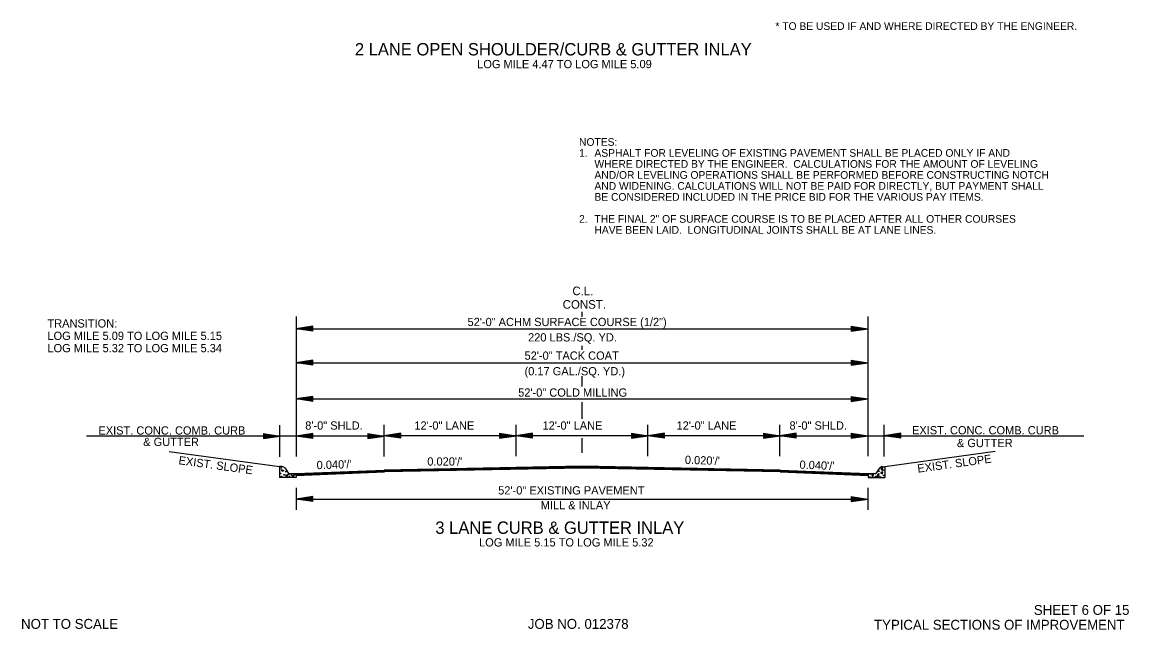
# Model space of a CAD drawing. Extents: x 542112 to 1930787, y -1968972 to 596640.
# Drawn here: x 546438 to 547445, y -1948192 to -1947639 of the extents above; entities that cross this region are included whole.
import ezdxf

# ---------------------------------------------------------------- set-up
doc = ezdxf.new("R2010")
doc.units = 0
for name, color, linetype in [('R_Border Notes', 7, 'Continuous'), ('R_Border Prem', 7, 'Continuous'), ('R_Draft', 7, 'Continuous')]:
    doc.layers.add(name, color=color, linetype=linetype)

msp = doc.modelspace()

# ---------------------------------------------------------------- linework, layer by layer
at = {"layer": 'R_Draft'}
for p, q in [((546947.1, -1947907), (546947.1, -1947902.6)), ((546687.1, -1947906.7), (546687.1, -1948034.1)), ((546702.1, -1947915.7), (546687.1, -1947918)), ((546687.1, -1947918), (547207.1, -1947918)), ((546702.1, -1947920.2), (546687.1, -1947918)), ((546702.1, -1947916.1), (546689.7, -1947918)), ((546702.1, -1947919.8), (546689.7, -1947918)), ((546702.1, -1947916.5), (546692.2, -1947918)), ((546702.1, -1947919.4), (546692.2, -1947918)), ((546702.1, -1947916.8), (546694.7, -1947918)), ((546702.1, -1947919.1), (546694.7, -1947918)), ((546702.1, -1947917.2), (546697.3, -1947918)), ((546702.1, -1947918.7), (546697.3, -1947918)), ((546702.1, -1947917.6), (546699.8, -1947918)), ((546702.1, -1947918.3), (546699.8, -1947918)), ((546702.1, -1947920.2), (546702.1, -1947915.7)), ((547192.1, -1947915.7), (547207.1, -1947918)), ((547192.1, -1947915.7), (547192.1, -1947920.2)), ((547192.1, -1947916.1), (547204.6, -1947918)), ((547192.1, -1947916.5), (547202, -1947918)), ((547192.1, -1947916.8), (547199.5, -1947918)), ((547192.1, -1947917.2), (547196.9, -1947918)), ((547192.1, -1947917.6), (547194.4, -1947918)), ((547192.1, -1947920.2), (547207.1, -1947918)), ((547192.1, -1947918.7), (547196.9, -1947918)), ((547192.1, -1947919.4), (547202, -1947918)), ((547192.1, -1947919.8), (547204.6, -1947918)), ((547192.1, -1947919.1), (547199.5, -1947918)), ((547192.1, -1947918.3), (547194.4, -1947918)), ((546947.1, -1947937.1), (546947.1, -1947933.4)), ((546702.1, -1947946.6), (546687.1, -1947948.8)), ((546687.1, -1947948.8), (547207.1, -1947948.8)), ((546702.1, -1947951.1), (546687.1, -1947948.8)), ((546702.1, -1947946.9), (546689.7, -1947948.8)), ((546702.1, -1947950.7), (546689.7, -1947948.8)), ((546702.1, -1947947.3), (546692.2, -1947948.8)), ((546702.1, -1947950.3), (546692.2, -1947948.8)), ((546702.1, -1947947.7), (546694.7, -1947948.8)), ((546702.1, -1947949.9), (546694.7, -1947948.8)), ((546702.1, -1947948.1), (546697.3, -1947948.8)), ((546702.1, -1947949.5), (546697.3, -1947948.8)), ((546702.1, -1947948.5), (546699.8, -1947948.8)), ((546702.1, -1947949.2), (546699.8, -1947948.8)), ((546702.1, -1947951.1), (546702.1, -1947946.6)), ((547192.1, -1947946.6), (547207.1, -1947948.8)), ((547192.1, -1947946.6), (547192.1, -1947951.1)), ((547192.1, -1947946.9), (547204.6, -1947948.8)), ((547192.1, -1947947.3), (547202, -1947948.8)), ((547192.1, -1947947.7), (547199.5, -1947948.8)), ((547192.1, -1947948.1), (547196.9, -1947948.8)), ((547192.1, -1947948.5), (547194.4, -1947948.8)), ((547192.1, -1947951.1), (547207.1, -1947948.8)), ((547192.1, -1947949.6), (547196.9, -1947948.8)), ((547192.1, -1947950.3), (547202, -1947948.8)), ((547192.1, -1947950.7), (547204.6, -1947948.8)), ((547192.1, -1947949.9), (547199.5, -1947948.8)), ((547192.1, -1947949.2), (547194.4, -1947948.8)), ((546947.1, -1947970.5), (546947.1, -1947961.2)), ((546702.1, -1947979.5), (546687.1, -1947981.8)), ((546687.1, -1947981.8), (547207.1, -1947981.8)), ((546702.1, -1947984), (546687.1, -1947981.8)), ((546702.1, -1947979.9), (546689.7, -1947981.8)), ((546702.1, -1947983.6), (546689.7, -1947981.8)), ((546702.1, -1947980.3), (546692.2, -1947981.8)), ((546702.1, -1947983.2), (546692.2, -1947981.8)), ((546702.1, -1947980.6), (546694.7, -1947981.8)), ((546702.1, -1947982.9), (546694.7, -1947981.8)), ((546702.1, -1947981), (546697.3, -1947981.8)), ((546702.1, -1947982.5), (546697.3, -1947981.8)), ((546702.1, -1947981.4), (546699.8, -1947981.8)), ((546702.1, -1947982.1), (546699.8, -1947981.8)), ((546702.1, -1947984), (546702.1, -1947979.5)), ((547192.1, -1947979.5), (547207.1, -1947981.8)), ((547192.1, -1947979.5), (547192.1, -1947984)), ((547192.1, -1947979.9), (547204.6, -1947981.8)), ((547192.1, -1947980.3), (547202, -1947981.8)), ((547192.1, -1947980.6), (547199.5, -1947981.8)), ((547192.1, -1947981), (547196.9, -1947981.8)), ((547192.1, -1947981.4), (547194.4, -1947981.8)), ((547192.1, -1947984), (547207.1, -1947981.8)), ((547192.1, -1947982.5), (547196.9, -1947981.8)), ((547192.1, -1947983.2), (547202, -1947981.8)), ((547192.1, -1947983.6), (547204.6, -1947981.8)), ((547192.1, -1947982.9), (547199.5, -1947981.8)), ((547192.1, -1947982.1), (547194.4, -1947981.8)), ((546947.1, -1947999.9), (546947.1, -1947984.7)), ((546657.1, -1948013.2), (546672.1, -1948015.5)), ((546657.1, -1948013.2), (546657.1, -1948017.7)), ((546657.1, -1948013.6), (546669.6, -1948015.5)), ((546657.1, -1948014), (546667.1, -1948015.5)), ((546672.1, -1948034.3), (546672.1, -1948005.6)), ((546702.1, -1948013.2), (546687.1, -1948015.5)), ((546702.1, -1948013.6), (546689.7, -1948015.5)), ((546702.1, -1948014), (546692.2, -1948015.5)), ((546702.1, -1948017.7), (546702.1, -1948013.2)), ((546752.1, -1948013.2), (546767.1, -1948015.5)), ((546752.1, -1948013.2), (546752.1, -1948017.7)), ((546752.1, -1948013.6), (546764.6, -1948015.5)), ((546752.1, -1948014), (546762.1, -1948015.5)), ((546767.1, -1948033.9), (546767.1, -1948005.4)), ((546767.1, -1948034.1), (546767.1, -1948005.4)), ((546782.1, -1948013), (546767.1, -1948015.3)), ((546782.1, -1948013.4), (546769.7, -1948015.3)), ((546782.1, -1948013.8), (546772.2, -1948015.3)), ((546782.1, -1948017.5), (546782.1, -1948013)), ((546872.1, -1948013), (546887.1, -1948015.3)), ((546872.1, -1948013), (546872.1, -1948017.5)), ((546872.1, -1948013.4), (546884.6, -1948015.3)), ((546872.1, -1948013.8), (546882.1, -1948015.3)), ((546887.1, -1948033.9), (546887.1, -1948005.4)), ((546902.1, -1948013), (546887.1, -1948015.3)), ((546902.1, -1948013.4), (546889.7, -1948015.3)), ((546902.1, -1948013.8), (546892.2, -1948015.3)), ((546902.1, -1948017.5), (546902.1, -1948013)), ((546992.1, -1948013), (547007.1, -1948015.3)), ((546992.1, -1948013), (546992.1, -1948017.5)), ((546992.1, -1948013.4), (547004.6, -1948015.3)), ((546992.1, -1948013.8), (547002.1, -1948015.3)), ((547007.1, -1948033.9), (547007.1, -1948005.4)), ((547022.1, -1948013), (547007.1, -1948015.3)), ((547022.1, -1948013.4), (547009.7, -1948015.3)), ((547022.1, -1948013.8), (547012.2, -1948015.3)), ((547022.1, -1948017.5), (547022.1, -1948013)), ((547112.1, -1948013), (547127.1, -1948015.3)), ((547112.1, -1948013), (547112.1, -1948017.5)), ((547112.1, -1948013.4), (547124.6, -1948015.3)), ((547112.1, -1948013.8), (547122.1, -1948015.3)), ((547127.1, -1948033.9), (547127.1, -1948005.4)), ((547142.1, -1948013), (547127.1, -1948015.3)), ((547142.1, -1948013.4), (547129.7, -1948015.3)), ((547142.1, -1948013.8), (547132.2, -1948015.3)), ((547142.1, -1948017.5), (547142.1, -1948013)), ((547192.1, -1948013), (547207.1, -1948015.3)), ((547192.1, -1948013), (547192.1, -1948017.5)), ((547192.1, -1948013.4), (547204.6, -1948015.3)), ((547192.1, -1948013.8), (547202.1, -1948015.3)), ((547222.1, -1948034.1), (547222.1, -1948005.4)), ((547237.1, -1948013), (547222.1, -1948015.3)), ((547237.1, -1948013.4), (547224.7, -1948015.3)), ((547237.1, -1948013.8), (547227.2, -1948015.3)), ((547237.1, -1948017.5), (547237.1, -1948013)), ((546687.1, -1948015.5), (546496.3, -1948015.5)), ((546657.1, -1948014.3), (546664.6, -1948015.5)), ((546657.1, -1948014.7), (546662, -1948015.5)), ((546657.1, -1948015.1), (546659.5, -1948015.5)), ((546657.1, -1948017.7), (546672.1, -1948015.5)), ((546657.1, -1948016.2), (546662, -1948015.5)), ((546657.1, -1948017), (546667.1, -1948015.5)), ((546657.1, -1948017.3), (546669.6, -1948015.5)), ((546657.1, -1948016.6), (546664.6, -1948015.5)), ((546657.1, -1948015.8), (546659.5, -1948015.5)), ((546767.1, -1948015.5), (546687.1, -1948015.5)), ((546702.1, -1948017.7), (546687.1, -1948015.5)), ((546702.1, -1948017.3), (546689.7, -1948015.5)), ((546702.1, -1948017), (546692.2, -1948015.5)), ((546702.1, -1948014.3), (546694.7, -1948015.5)), ((546702.1, -1948016.6), (546694.7, -1948015.5)), ((546702.1, -1948014.7), (546697.3, -1948015.5)), ((546702.1, -1948016.2), (546697.3, -1948015.5)), ((546702.1, -1948015.1), (546699.8, -1948015.5)), ((546702.1, -1948015.8), (546699.8, -1948015.5)), ((546752.1, -1948014.3), (546759.6, -1948015.5)), ((546752.1, -1948014.7), (546757, -1948015.5)), ((546752.1, -1948015.1), (546754.5, -1948015.5)), ((546752.1, -1948017.7), (546767.1, -1948015.5)), ((546752.1, -1948016.2), (546757, -1948015.5)), ((546752.1, -1948017), (546762.1, -1948015.5)), ((546752.1, -1948017.3), (546764.6, -1948015.5)), ((546752.1, -1948016.6), (546759.6, -1948015.5)), ((546752.1, -1948015.8), (546754.5, -1948015.5)), ((546887.1, -1948015.3), (546767.1, -1948015.3)), ((546782.1, -1948017.5), (546767.1, -1948015.3)), ((546782.1, -1948017.2), (546769.7, -1948015.3)), ((546782.1, -1948016.8), (546772.2, -1948015.3)), ((546782.1, -1948014.2), (546774.7, -1948015.3)), ((546782.1, -1948016.4), (546774.7, -1948015.3)), ((546782.1, -1948014.6), (546777.3, -1948015.3)), ((546782.1, -1948016), (546777.3, -1948015.3)), ((546782.1, -1948014.9), (546779.8, -1948015.3)), ((546782.1, -1948015.6), (546779.8, -1948015.3)), ((546872.1, -1948014.2), (546879.6, -1948015.3)), ((546872.1, -1948014.6), (546877, -1948015.3)), ((546872.1, -1948014.9), (546874.5, -1948015.3)), ((546872.1, -1948017.5), (546887.1, -1948015.3)), ((546872.1, -1948016), (546877, -1948015.3)), ((546872.1, -1948016.8), (546882.1, -1948015.3)), ((546872.1, -1948017.2), (546884.6, -1948015.3)), ((546872.1, -1948016.4), (546879.6, -1948015.3)), ((546872.1, -1948015.6), (546874.5, -1948015.3)), ((547007.1, -1948015.3), (546887.1, -1948015.3)), ((546902.1, -1948017.5), (546887.1, -1948015.3)), ((546902.1, -1948017.2), (546889.7, -1948015.3)), ((546902.1, -1948016.8), (546892.2, -1948015.3)), ((546902.1, -1948014.2), (546894.7, -1948015.3)), ((546902.1, -1948016.4), (546894.7, -1948015.3)), ((546902.1, -1948014.6), (546897.3, -1948015.3)), ((546902.1, -1948016), (546897.3, -1948015.3)), ((546902.1, -1948014.9), (546899.8, -1948015.3)), ((546902.1, -1948015.6), (546899.8, -1948015.3)), ((546947.1, -1948030.7), (546947.1, -1948017.4)), ((546992.1, -1948014.2), (546999.6, -1948015.3)), ((546992.1, -1948014.6), (546997, -1948015.3)), ((546992.1, -1948014.9), (546994.5, -1948015.3)), ((546992.1, -1948017.5), (547007.1, -1948015.3)), ((546992.1, -1948016), (546997, -1948015.3)), ((546992.1, -1948016.8), (547002.1, -1948015.3)), ((546992.1, -1948017.2), (547004.6, -1948015.3)), ((546992.1, -1948016.4), (546999.6, -1948015.3)), ((546992.1, -1948015.6), (546994.5, -1948015.3)), ((547127.1, -1948015.3), (547007.1, -1948015.3)), ((547022.1, -1948017.5), (547007.1, -1948015.3)), ((547022.1, -1948017.2), (547009.7, -1948015.3)), ((547022.1, -1948016.8), (547012.2, -1948015.3)), ((547022.1, -1948014.2), (547014.7, -1948015.3)), ((547022.1, -1948016.4), (547014.7, -1948015.3)), ((547022.1, -1948014.6), (547017.3, -1948015.3)), ((547022.1, -1948016), (547017.3, -1948015.3)), ((547022.1, -1948014.9), (547019.8, -1948015.3)), ((547022.1, -1948015.6), (547019.8, -1948015.3)), ((547112.1, -1948014.2), (547119.6, -1948015.3)), ((547112.1, -1948014.6), (547117, -1948015.3)), ((547112.1, -1948014.9), (547114.5, -1948015.3)), ((547112.1, -1948017.5), (547127.1, -1948015.3)), ((547112.1, -1948016), (547117, -1948015.3)), ((547112.1, -1948016.8), (547122.1, -1948015.3)), ((547112.1, -1948017.2), (547124.6, -1948015.3)), ((547112.1, -1948016.4), (547119.6, -1948015.3)), ((547112.1, -1948015.6), (547114.5, -1948015.3)), ((547127.1, -1948015.3), (547207.1, -1948015.3)), ((547142.1, -1948017.5), (547127.1, -1948015.3)), ((547142.1, -1948017.2), (547129.7, -1948015.3)), ((547142.1, -1948016.8), (547132.2, -1948015.3)), ((547142.1, -1948014.2), (547134.7, -1948015.3)), ((547142.1, -1948016.4), (547134.7, -1948015.3)), ((547142.1, -1948014.6), (547137.3, -1948015.3)), ((547142.1, -1948016), (547137.3, -1948015.3)), ((547142.1, -1948014.9), (547139.8, -1948015.3)), ((547142.1, -1948015.6), (547139.8, -1948015.3)), ((547192.1, -1948014.2), (547199.6, -1948015.3)), ((547192.1, -1948014.6), (547197, -1948015.3)), ((547192.1, -1948014.9), (547194.5, -1948015.3)), ((547192.1, -1948017.5), (547207.1, -1948015.3)), ((547192.1, -1948016), (547197, -1948015.3)), ((547192.1, -1948016.8), (547202.1, -1948015.3)), ((547192.1, -1948017.2), (547204.6, -1948015.3)), ((547192.1, -1948016.4), (547199.6, -1948015.3)), ((547192.1, -1948015.6), (547194.5, -1948015.3)), ((547207.1, -1948015.3), (547403.8, -1948015.3)), ((547237.1, -1948017.5), (547222.1, -1948015.3)), ((547237.1, -1948017.2), (547224.7, -1948015.3)), ((547237.1, -1948016.8), (547227.2, -1948015.3)), ((547237.1, -1948014.2), (547229.7, -1948015.3)), ((547237.1, -1948016.4), (547229.7, -1948015.3)), ((547237.1, -1948014.6), (547232.3, -1948015.3)), ((547237.1, -1948016), (547232.3, -1948015.3)), ((547237.1, -1948014.9), (547234.8, -1948015.3)), ((547237.1, -1948015.6), (547234.8, -1948015.3)), ((546571.4, -1948029.5), (546671.9, -1948043.3)), ((547323.1, -1948029.6), (547222.6, -1948043.4)), ((546674.1, -1948043.3), (546671.9, -1948043.3)), ((546671.9, -1948043.3), (546671.9, -1948053.2)), ((546947.1, -1948042.9), (546767.1, -1948046.5)), ((546947.2, -1948043.2), (546767.2, -1948046.8)), ((546947.2, -1948043.5), (546767.2, -1948047.1)), ((546947.2, -1948043.8), (546767.2, -1948047.4)), ((546947.2, -1948044.1), (546767.2, -1948047.7)), ((547127.3, -1948046.5), (546947.1, -1948042.9)), ((547127.3, -1948046.8), (546947.1, -1948043.2)), ((547127.3, -1948047.1), (546947.1, -1948043.5)), ((547127.3, -1948047.4), (546947.1, -1948043.8)), ((547127.3, -1948047.7), (546947.1, -1948044.1)), ((547220.5, -1948043.4), (547222.6, -1948043.4)), ((547222.6, -1948043.4), (547222.6, -1948053.2)), ((546686.9, -1948053.2), (546671.9, -1948053.2)), ((546676.9, -1948044.8), (546680, -1948049.7)), ((546680, -1948049.7), (546686.9, -1948049.7)), ((546686.9, -1948049.7), (546767.1, -1948046.5)), ((546686.9, -1948050), (546767.2, -1948046.8)), ((546686.9, -1948050.3), (546767.2, -1948047.1)), ((546686.9, -1948050.6), (546767.2, -1948047.4)), ((546686.9, -1948050.9), (546767.2, -1948047.7)), ((546686.9, -1948051.2), (546767.2, -1948048)), ((546686.9, -1948051.4), (546767.2, -1948048.2)), ((546686.9, -1948049.7), (546686.9, -1948051.4)), ((546686.9, -1948049.7), (546686.9, -1948053.2)), ((546947.2, -1948044.4), (546767.2, -1948048)), ((546947.2, -1948044.6), (546767.2, -1948048.2)), ((547127.3, -1948048), (546947.1, -1948044.4)), ((547127.3, -1948048.2), (546947.1, -1948044.6)), ((547127.3, -1948046.5), (547207.6, -1948049.7)), ((547127.3, -1948046.8), (547207.6, -1948050)), ((547127.3, -1948047.1), (547207.6, -1948050.3)), ((547127.3, -1948047.4), (547207.6, -1948050.6)), ((547127.3, -1948047.7), (547207.6, -1948050.9)), ((547127.3, -1948048), (547207.6, -1948051.2)), ((547127.3, -1948048.2), (547207.6, -1948051.4)), ((547207.6, -1948049.7), (547207.6, -1948051.4)), ((547207.6, -1948051.4), (547207.6, -1948049.7)), ((547207.6, -1948049.7), (547207.6, -1948051.4)), ((547207.6, -1948051.4), (547207.6, -1948049.7)), ((547207.6, -1948049.7), (547214.6, -1948049.7)), ((547207.6, -1948049.7), (547207.6, -1948053.2)), ((547207.6, -1948053.2), (547222.6, -1948053.2)), ((547217.6, -1948044.9), (547214.6, -1948049.7)), ((546687.1, -1948062.5), (546687.1, -1948082.5)), ((547207.1, -1948062.5), (547207.1, -1948082.5)), ((546702.1, -1948070.5), (546687.1, -1948072.8)), ((546687.1, -1948072.8), (547207.1, -1948072.8)), ((546702.1, -1948075), (546687.1, -1948072.8)), ((546702.1, -1948070.9), (546689.7, -1948072.8)), ((546702.1, -1948074.6), (546689.7, -1948072.8)), ((546702.1, -1948071.3), (546692.2, -1948072.8)), ((546702.1, -1948074.2), (546692.2, -1948072.8)), ((546702.1, -1948071.6), (546694.7, -1948072.8)), ((546702.1, -1948073.9), (546694.7, -1948072.8)), ((546702.1, -1948072), (546697.3, -1948072.8)), ((546702.1, -1948073.5), (546697.3, -1948072.8)), ((546702.1, -1948072.4), (546699.8, -1948072.8)), ((546702.1, -1948073.1), (546699.8, -1948072.8)), ((546702.1, -1948075), (546702.1, -1948070.5)), ((547192.1, -1948070.5), (547207.1, -1948072.8)), ((547192.1, -1948070.5), (547192.1, -1948075)), ((547192.1, -1948070.9), (547204.6, -1948072.8)), ((547192.1, -1948071.3), (547202.1, -1948072.8)), ((547192.1, -1948071.6), (547199.6, -1948072.8)), ((547192.1, -1948072), (547197, -1948072.8)), ((547192.1, -1948072.4), (547194.5, -1948072.8)), ((547192.1, -1948075), (547207.1, -1948072.8)), ((547192.1, -1948073.5), (547197, -1948072.8)), ((547192.1, -1948074.2), (547202.1, -1948072.8)), ((547192.1, -1948074.6), (547204.6, -1948072.8)), ((547192.1, -1948073.9), (547199.6, -1948072.8)), ((547192.1, -1948073.1), (547194.5, -1948072.8))]:
    msp.add_line(p, q, dxfattribs=at)
for points in [[(547207.1, -1947906.7), (547207.1, -1948033.9)], [(546675.8, -1948046.8), (546674.1, -1948047.9), (546673.7, -1948046.1), (546675.6, -1948046.8)], [(546678.6, -1948052.7), (546677.5, -1948051), (546679.3, -1948050.6), (546678.6, -1948052.5)], [(546684.3, -1948053.1), (546683.2, -1948051.3), (546684.9, -1948050.9), (546684.3, -1948052.8)], [(547211.3, -1948053.2), (547212.5, -1948051.4), (547210.7, -1948051), (547211.3, -1948052.9)], [(547216.4, -1948052.9), (547217.6, -1948051.1), (547215.8, -1948050.8), (547216.4, -1948052.7)], [(547218.7, -1948048.8), (547220.4, -1948049.9), (547220.8, -1948048.2), (547218.9, -1948048.8)], [(547219.6, -1948046.6), (547220.8, -1948044.8), (547219, -1948044.4), (547219.6, -1948046.3)]]:
    msp.add_lwpolyline(points, dxfattribs=at)
for centre in [(546673.4, -1948044.5), (546672.8, -1948049.5), (546673.6, -1948052.5), (546676.1, -1948050.8), (546677.4, -1948047.9), (546680.3, -1948050.2), (546680.7, -1948052.4), (546682.6, -1948051), (546685.5, -1948050.8), (547209, -1948052.9), (547209.6, -1948050.1), (547211.8, -1948050.6), (547214.4, -1948052.4), (547217.1, -1948049.9), (547217.3, -1948047.4), (547218.4, -1948052.8), (547221.1, -1948046.5), (547221.7, -1948051.5)]:
    msp.add_circle(centre, 0.339, dxfattribs=at)
for centre, start, end in [((546674.1, -1948046.6), 32.2756, 91.1196), ((547220.4, -1948046.7), 88.8804, 147.7244)]:
    msp.add_arc(centre, 3.26, start, end, dxfattribs=at)

# ---------------------------------------------------------------- texts
at = {"layer": 'R_Border Notes'}
for s, height, p in [('NOTES: ', 7, (546944.4, -1947751.5)), ('1.', 7, (546944.4, -1947761.5)), ('ASPHALT FOR LEVELING OF EXISTING PAVEMENT SHALL BE PLACED ONLY IF AND', 7, (546958.4, -1947761.5)), ('WHERE DIRECTED BY THE ENGINEER.  CALCULATIONS FOR THE AMOUNT OF LEVELING', 7, (546958.4, -1947771.5)), ('AND/OR LEVELING OPERATIONS SHALL BE PERFORMED BEFORE CONSTRUCTING NOTCH', 7, (546958.4, -1947781.5)), ('AND WIDENING. CALCULATIONS WILL NOT BE PAID FOR DIRECTLY, BUT PAYMENT SHALL', 7, (546958.4, -1947791.5)), ('BE CONSIDERED INCLUDED IN THE PRICE BID FOR THE VARIOUS PAY ITEMS.', 7, (546958.4, -1947801.5)), ('2.', 7, (546944.4, -1947821.5)), ('THE FINAL 2" OF SURFACE COURSE IS TO BE PLACED AFTER ALL OTHER COURSES', 7, (546958.4, -1947821.5)), ('HAVE BEEN LAID.  LONGITUDINAL JOINTS SHALL BE AT LANE LINES.', 7, (546958.4, -1947831.5)), ('SHEET 6 OF 15', 9, (547358.3, -1948178.2)), ('NOT TO SCALE', 9, (546436.6, -1948190.9)), ('TYPICAL SECTIONS OF IMPROVEMENT', 9, (547212.8, -1948191.7))]:
    msp.add_text(s, height=height, dxfattribs=at).set_placement(p)
msp.add_text('JOB NO. 012378', height=9, rotation=360, dxfattribs=at).set_placement((546897.8, -1948190.9))
at = {"layer": 'R_Border Prem'}
msp.add_text('* TO BE USED IF AND WHERE DIRECTED BY THE ENGINEER.', height=7, dxfattribs=at).set_placement((547123.1, -1947646.1))
at = {"layer": 'R_Draft'}
for s, height, p in [('2 LANE OPEN SHOULDER/CURB & GUTTER INLAY', 11.25, (546740.4, -1947669.3)), ('LOG MILE 4.47 TO LOG MILE 5.09', 7.5, (546851.7, -1947680.9)), ('C.L.', 7.8, (546938.3, -1947887.4)), ('CONST.', 7.8, (546929.5, -1947899.7)), ('TRANSITION:', 7.5, (546460.6, -1947916.8)), ('52\'-0" ACHM SURFACE COURSE (1/2")', 7.5, (546842.9, -1947915.5)), ('LOG MILE 5.09 TO LOG MILE 5.15', 7.5, (546460.6, -1947928.1)), ('220 LBS./SQ. YD. ', 7.5, (546898, -1947929.5)), ('LOG MILE 5.32 TO LOG MILE 5.34', 7.5, (546460.6, -1947939.3)), ('52\'-0" TACK COAT', 7.5, (546894.8, -1947946.1)), ('(0.17 GAL./SQ. YD.)', 7.5, (546894.8, -1947960.3)), ('52\'-0" COLD MILLING', 7.5, (546889, -1947979.7)), ('8\'-0" SHLD.', 7.5, (546695.2, -1948009.7)), ('12\'-0" LANE', 7.5, (546794.5, -1948009.7)), ('12\'-0" LANE', 7.5, (546911.1, -1948009.7)), ('12\'-0" LANE', 7.5, (547033.1, -1948009.7)), ('8\'-0" SHLD.', 7.5, (547135.9, -1948009.7)), ('EXIST. CONC. COMB. CURB', 7.5, (546507, -1948014.2)), ('EXIST. CONC. COMB. CURB', 7.5, (547247.4, -1948014)), ('& GUTTER ', 7.5, (546547.8, -1948024.6)), ('& GUTTER ', 7.5, (547288.3, -1948025.6)), ("0.020'/'", 7.5, (546806.3, -1948042.4)), ('52\'-0" EXISTING PAVEMENT', 7.5, (546870.8, -1948068.7)), ('MILL & INLAY', 7.5, (546909.5, -1948082.2)), ('3 LANE CURB & GUTTER INLAY', 11.25, (546813.6, -1948104.5)), ('LOG MILE 5.15 TO LOG MILE 5.32', 7.5, (546853.4, -1948116))]:
    msp.add_text(s, height=height, dxfattribs=at).set_placement(p)
for s, rotation, p in [('EXIST. SLOPE', 352.1682, (546579.6, -1948041.1)), ("0.020'/'", 358.0607, (547040.6, -1948040.8)), ('EXIST. SLOPE', 7.8318, (547252.8, -1948048.9)), ("0.040'/'", 1.7023, (546705.7, -1948045.7)), ("0.040'/'", 357.8168, (547144.9, -1948045.2))]:
    msp.add_text(s, height=7.5, rotation=rotation, dxfattribs=at).set_placement(p)

doc.saveas('drawing.dxf')
